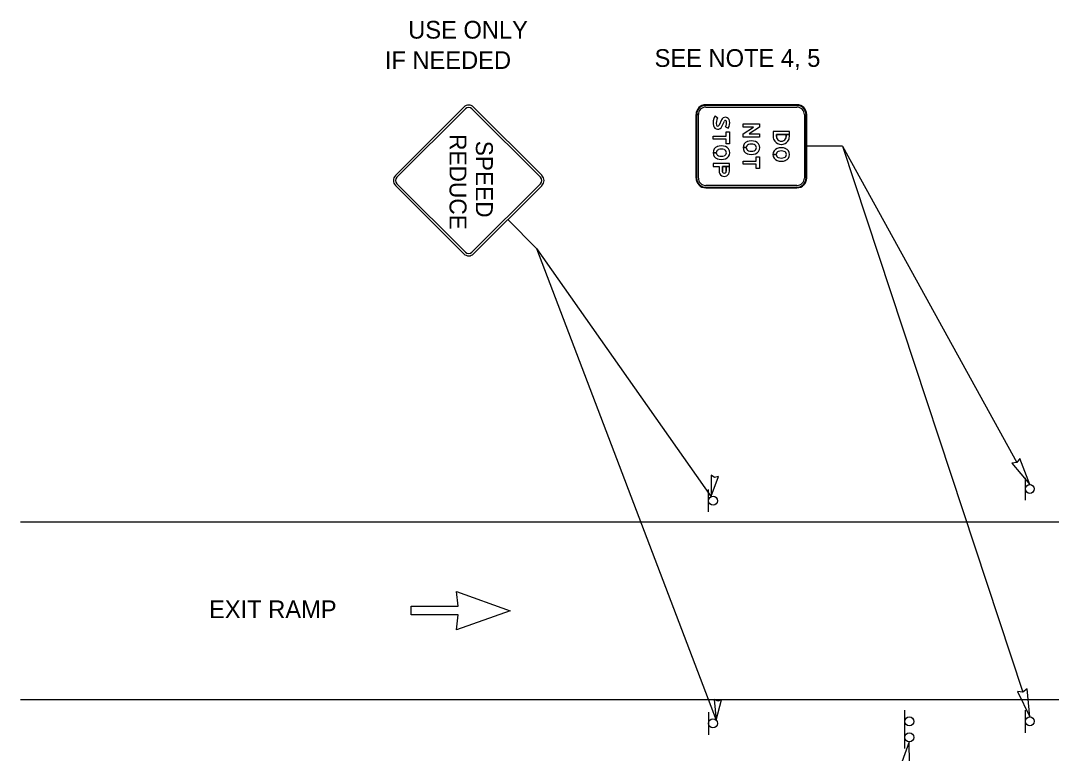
# Model space of a CAD drawing. Extents: x 46672 to 47298, y 5424 to 5742.
# Drawn here: x 47010.2 to 47173.2, y 5620.1 to 5736 of the extents above; entities that cross this region are included whole.
import ezdxf

# ---------------------------------------------------------------- set-up
doc = ezdxf.new("R2010")
doc.units = 0
for name, color, linetype in [('GSBWFill', 7, 'Continuous'), ('SheetBorder_dp', 7, 'Continuous'), ('SheetLines_dp', 7, 'Continuous'), ('TextAlert', 7, 'Continuous'), ('TextMisc', 7, 'Continuous'), ('TextNotes', 7, 'Continuous')]:
    doc.layers.add(name, color=color, linetype=linetype)

msp = doc.modelspace()

# ---------------------------------------------------------------- linework, layer by layer
at = {"layer": 'GSBWFill'}
for p, q in [((47010.15, 5656.76), (47280.21, 5656.76)), ((47010.15, 5628.64), (47280.21, 5628.64))]:
    msp.add_line(p, q, dxfattribs=at)
at = {"layer": 'SheetLines_dp'}
for p, q in [((47140.16, 5716.16), (47134.47, 5716.15)), ((47140.16, 5716.16), (47168.68, 5629.83)), ((47140.16, 5716.16), (47167.73, 5666.13)), ((47091.75, 5700.01), (47087.2, 5704.56)), ((47091.75, 5700.01), (47120.15, 5625.36)), ((47091.75, 5700.01), (47119.36, 5660.72))]:
    msp.add_line(p, q, dxfattribs=at)
for points in [[(47169.77, 5662.66), (47168.21, 5666.79), (47167.73, 5666.13), (47166.9, 5666.01)], [(47119.39, 5660.79), (47120.51, 5663.92), (47119.91, 5663.78), (47119.38, 5664.11)], [(47169.77, 5625.9), (47169.33, 5630.34), (47168.68, 5629.83), (47167.84, 5629.93)], [(47120.15, 5625.36), (47120.98, 5628.58), (47120.4, 5628.39), (47119.84, 5628.67)], [(47150.7, 5621.96), (47149.54, 5618.72), (47150.16, 5618.86), (47150.71, 5618.52)]]:
    msp.add_lwpolyline(points, close=True, dxfattribs=at)
at = {"layer": 'TextAlert'}
for p, q in [((47079.33, 5643.4), (47079.09, 5645.74)), ((47079.09, 5645.74), (47087.58, 5642.7)), ((47071.9, 5642.04), (47071.91, 5643.42)), ((47071.91, 5643.42), (47079.33, 5643.4)), ((47087.58, 5642.7), (47079.08, 5639.69)), ((47079.33, 5642.03), (47071.9, 5642.04)), ((47079.08, 5639.69), (47079.33, 5642.03))]:
    msp.add_line(p, q, dxfattribs=at)
at = {"layer": 'TextMisc'}
for p, q in [((47169.05, 5663.72), (47169.04, 5660.16)), ((47118.95, 5658.33), (47118.95, 5661.88)), ((47118.93, 5626.62), (47118.92, 5623.07)), ((47149.98, 5620.9), (47149.98, 5626.94)), ((47169.04, 5626.96), (47169.04, 5623.4))]:
    msp.add_line(p, q, dxfattribs=at)
for centre in [(47169.77, 5661.96), (47119.67, 5660.09), (47119.65, 5624.87), (47150.7, 5625.18), (47169.77, 5625.2), (47150.7, 5622.66)]:
    msp.add_circle(centre, 0.703, dxfattribs=at)
at = {"layer": 'TextNotes'}
for p, q in [((47069.42, 5711.52), (47080.24, 5722.35)), ((47081.79, 5722.35), (47092.62, 5711.52)), ((47132.93, 5722.72), (47118.52, 5722.72)), ((47132.93, 5722.72), (47118.52, 5722.72)), ((47118.52, 5722.69), (47132.93, 5722.69)), ((47132.93, 5722.62), (47118.52, 5722.62)), ((47118.52, 5722.35), (47132.93, 5722.35)), ((47069.67, 5711.26), (47080.5, 5722.09)), ((47081.53, 5722.09), (47092.36, 5711.26)), ((47116.97, 5721.17), (47116.97, 5711.14)), ((47116.97, 5721.17), (47117, 5721.17)), ((47117, 5721.17), (47116.97, 5721.17)), ((47116.97, 5721.17), (47116.97, 5711.14)), ((47117, 5711.14), (47117, 5721.17)), ((47117.07, 5721.17), (47117.34, 5721.17)), ((47117.07, 5721.16), (47117.07, 5711.14)), ((47117.34, 5721.16), (47117.07, 5721.16)), ((47117.34, 5711.14), (47117.34, 5721.16)), ((47120.39, 5720.65), (47119.96, 5720.91)), ((47120.39, 5720.65), (47119.96, 5720.91)), ((47120.39, 5720.65), (47119.96, 5720.91)), ((47134.11, 5721.17), (47134.11, 5711.14)), ((47134.38, 5711.14), (47134.38, 5721.17)), ((47134.45, 5721.17), (47134.45, 5711.14)), ((47134.47, 5711.14), (47134.47, 5721.17)), ((47134.47, 5711.14), (47134.47, 5721.17)), ((47120.99, 5720.34), (47120.61, 5719.48)), ((47120.99, 5720.34), (47120.61, 5719.48)), ((47120.99, 5720.34), (47120.61, 5719.48)), ((47121.08, 5719.27), (47121.45, 5720.14)), ((47121.08, 5719.27), (47121.45, 5720.14)), ((47121.08, 5719.27), (47121.45, 5720.14)), ((47121.63, 5719.25), (47122.08, 5719.01)), ((47121.63, 5719.25), (47122.08, 5719.01)), ((47121.63, 5719.25), (47122.08, 5719.01)), ((47129.19, 5717.68), (47129.19, 5717.68)), ((47129.7, 5717.68), (47129.7, 5718.01)), ((47129.7, 5717.68), (47129.7, 5718.01)), ((47129.7, 5717.68), (47129.7, 5717.68)), ((47124.4, 5715.94), (47124.91, 5715.94)), ((47124.91, 5715.94), (47124.4, 5715.94)), ((47124.4, 5715.94), (47124.91, 5715.94)), ((47124.91, 5715.94), (47124.4, 5715.94)), ((47119.67, 5715.14), (47120.18, 5715.14)), ((47120.18, 5715.14), (47119.67, 5715.14)), ((47119.67, 5715.14), (47120.18, 5715.14)), ((47120.18, 5715.14), (47119.67, 5715.14)), ((47129.14, 5714.86), (47129.65, 5714.86)), ((47129.65, 5714.86), (47129.14, 5714.86)), ((47129.14, 5714.86), (47129.65, 5714.86)), ((47129.65, 5714.86), (47129.14, 5714.86)), ((47120.63, 5712.96), (47120.63, 5712.2)), ((47121.14, 5712.96), (47121.14, 5712.23)), ((47080.24, 5699.15), (47069.42, 5709.97)), ((47080.5, 5699.4), (47069.67, 5710.23)), ((47092.36, 5710.23), (47081.53, 5699.4)), ((47092.62, 5709.97), (47081.79, 5699.15)), ((47132.93, 5709.95), (47118.52, 5709.95)), ((47118.52, 5709.68), (47132.93, 5709.68)), ((47132.93, 5709.62), (47118.52, 5709.62)), ((47118.52, 5709.59), (47132.93, 5709.59)), ((47118.52, 5709.59), (47132.93, 5709.59))]:
    msp.add_line(p, q, dxfattribs=at)
for points in [[(47127, 5719.69), (47127, 5719.18), (47125.39, 5718.13), (47127, 5718.13), (47127, 5717.62), (47124.45, 5717.62), (47124.45, 5718.12), (47126.07, 5719.18), (47124.45, 5719.18), (47124.45, 5719.69)], [(47127, 5719.69), (47127, 5719.18), (47125.39, 5718.13), (47127, 5718.13), (47127, 5717.62), (47124.45, 5717.62), (47124.45, 5718.12), (47126.07, 5719.18), (47124.45, 5719.18), (47124.45, 5719.69)], [(47127, 5719.69), (47127, 5719.18), (47125.39, 5718.13), (47127, 5718.13), (47127, 5717.62), (47124.45, 5717.62), (47124.45, 5718.12), (47126.07, 5719.18), (47124.45, 5719.18), (47124.45, 5719.69)], [(47119.71, 5717.26), (47119.71, 5717.77), (47121.75, 5717.77), (47121.75, 5718.46), (47122.26, 5718.46), (47122.26, 5716.57), (47121.75, 5716.57), (47121.75, 5717.26)], [(47119.71, 5717.26), (47119.71, 5717.77), (47121.75, 5717.77), (47121.75, 5718.46), (47122.26, 5718.46), (47122.26, 5716.57), (47121.75, 5716.57), (47121.75, 5717.26)], [(47119.71, 5717.26), (47119.71, 5717.77), (47121.75, 5717.77), (47121.75, 5718.46), (47122.26, 5718.46), (47122.26, 5716.57), (47121.75, 5716.57), (47121.75, 5717.26)], [(47124.45, 5713.31), (47124.45, 5713.82), (47126.49, 5713.82), (47126.49, 5714.51), (47127, 5714.51), (47127, 5712.62), (47126.49, 5712.62), (47126.49, 5713.31)], [(47124.45, 5713.31), (47124.45, 5713.82), (47126.49, 5713.82), (47126.49, 5714.51), (47127, 5714.51), (47127, 5712.62), (47126.49, 5712.62), (47126.49, 5713.31)], [(47124.45, 5713.31), (47124.45, 5713.82), (47126.49, 5713.82), (47126.49, 5714.51), (47127, 5714.51), (47127, 5712.62), (47126.49, 5712.62), (47126.49, 5713.31)]]:
    msp.add_lwpolyline(points, close=True, dxfattribs=at)
for points in [[(47131.74, 5717.68), (47131.74, 5718.51), (47129.19, 5718.51), (47129.19, 5717.68)], [(47129.7, 5718.01), (47131.74, 5718.01), (47131.74, 5718.51), (47129.19, 5718.51), (47129.19, 5717.68)], [(47129.7, 5718.01), (47131.74, 5718.01), (47131.74, 5718.51), (47129.19, 5718.51), (47129.19, 5717.68)], [(47131.23, 5717.68), (47131.23, 5718.01), (47129.7, 5718.01), (47129.7, 5717.68)], [(47131.74, 5717.68), (47131.74, 5718.01), (47131.23, 5718.01), (47131.23, 5717.68)], [(47131.74, 5717.68), (47131.74, 5718.01), (47131.23, 5718.01), (47131.23, 5717.68)], [(47122.26, 5712.2), (47122.26, 5713.46), (47119.71, 5713.46), (47119.71, 5712.96), (47120.63, 5712.96)], [(47122.26, 5713.46), (47119.71, 5713.46), (47119.71, 5712.96), (47120.63, 5712.96), (47120.63, 5712.2)], [(47122.26, 5713.46), (47119.71, 5713.46), (47119.71, 5712.96), (47120.63, 5712.96), (47120.63, 5712.2)], [(47121.14, 5712.23), (47121.14, 5712.96), (47122.26, 5712.96), (47122.26, 5713.46)], [(47121.14, 5712.23), (47121.14, 5712.96), (47122.26, 5712.96), (47122.26, 5713.46)], [(47121.75, 5712.23), (47121.75, 5712.96), (47121.14, 5712.96)], [(47122.26, 5712.2), (47122.26, 5712.96), (47121.75, 5712.96), (47121.75, 5712.23)], [(47122.26, 5712.2), (47122.26, 5712.96), (47121.75, 5712.96), (47121.75, 5712.23)]]:
    msp.add_lwpolyline(points, dxfattribs=at)
for centre, radius, start, end in [((47081.02, 5721.58), 1.09, 45, 135), ((47081.02, 5721.58), 0.729, 45, 135), ((47118.52, 5721.17), 1.55, 90, 180), ((47118.52, 5721.17), 1.55, 90, 180), ((47118.52, 5721.17), 1.52, 90, 180), ((47118.52, 5721.17), 1.46, 90, 180), ((47118.52, 5721.17), 1.18, 90, 180), ((47132.93, 5721.17), 1.55, 0, 90), ((47132.93, 5721.17), 1.55, 0, 90), ((47132.93, 5721.17), 1.52, 0, 90), ((47132.93, 5721.17), 1.46, 0, 90), ((47132.93, 5721.17), 1.18, 0, 90), ((47121.66, 5719.88), 1.99, 148.7193, 194.4775), ((47121.66, 5719.88), 1.99, 148.7193, 194.4775), ((47121.66, 5719.88), 1.99, 148.7193, 194.4775), ((47121.66, 5719.88), 1.48, 148.7193, 194.4775), ((47121.66, 5719.88), 1.48, 148.7193, 194.4775), ((47121.66, 5719.88), 1.48, 148.7193, 194.4775), ((47121.61, 5720.07), 0.676, 9.4877, 156.3243), ((47121.61, 5720.07), 0.676, 9.4877, 156.3243), ((47121.61, 5720.07), 0.676, 9.4877, 156.3243), ((47120.42, 5719.56), 0.714, 194.4775, 336.3243), ((47120.42, 5719.56), 0.714, 194.4775, 336.3243), ((47120.42, 5719.56), 0.714, 194.4775, 336.3243), ((47120.42, 5719.56), 0.204, 194.4775, 336.3243), ((47120.42, 5719.56), 0.204, 194.4775, 336.3243), ((47120.42, 5719.56), 0.204, 194.4775, 336.3243), ((47121.61, 5720.07), 0.166, 9.4877, 156.3243), ((47121.61, 5720.07), 0.166, 9.4877, 156.3243), ((47121.61, 5720.07), 0.166, 9.4877, 156.3243), ((47120.46, 5719.88), 1.33, 331.8214, 9.4877), ((47120.46, 5719.88), 1.33, 331.8214, 9.4877), ((47120.46, 5719.88), 1.33, 331.8214, 9.4877), ((47120.46, 5719.88), 1.84, 331.8214, 9.4877), ((47120.46, 5719.88), 1.84, 331.8214, 9.4877), ((47120.46, 5719.88), 1.84, 331.8214, 9.4877), ((47070.19, 5710.75), 1.09, 135, 225), ((47070.19, 5710.75), 0.729, 135, 225), ((47091.84, 5710.75), 0.729, 315, 45), ((47091.84, 5710.75), 1.09, 315, 45), ((47118.52, 5711.14), 1.55, 180, 270), ((47118.52, 5711.14), 1.55, 180, 270), ((47118.52, 5711.14), 1.52, 180, 270), ((47118.52, 5711.14), 1.46, 180, 270), ((47118.52, 5711.14), 1.18, 180, 270), ((47132.93, 5711.14), 1.46, 270, 0), ((47132.93, 5711.14), 1.18, 270, 0), ((47132.93, 5711.14), 1.55, 270, 0), ((47132.93, 5711.14), 1.52, 270, 0), ((47132.93, 5711.14), 1.55, 270, 0), ((47081.02, 5699.92), 0.729, 225, 315), ((47081.02, 5699.92), 1.09, 225, 315)]:
    msp.add_arc(centre, radius, start, end, dxfattribs=at)
for centre, major_axis, ratio, start_param, end_param in [((47130.3, 5717.65), (1.12, 0), 0.992015, 3.111301, 3.802985), ((47130.3, 5717.65), (1.12, 0), 0.992015, 3.111301, 3.802985), ((47130.3, 5717.65), (1.12, 0), 0.992015, 3.111301, 3.802985), ((47130.39, 5717.67), (0.69, 0), 0.992015, 3.123742, 3.672538), ((47130.39, 5717.67), (0.69, 0), 0.992015, 3.123742, 3.672538), ((47130.39, 5717.67), (0.69, 0), 0.992015, 3.123742, 3.672538), ((47130.44, 5717.71), (0.762, 0), 0.992015, 3.689617, 4.738495), ((47130.44, 5717.71), (0.762, 0), 0.992015, 3.689617, 4.738495), ((47130.44, 5717.71), (0.762, 0), 0.992015, 3.689617, 4.738495), ((47130.48, 5717.71), (0.762, 0), 0.992015, 4.686283, 5.735161), ((47130.48, 5717.71), (0.762, 0), 0.992015, 4.686283, 5.735161), ((47130.48, 5717.71), (0.762, 0), 0.992015, 4.686283, 5.735161), ((47130.54, 5717.67), (0.69, 0), 0.992015, 5.75224, 6.301036), ((47130.54, 5717.67), (0.69, 0), 0.992015, 5.75224, 6.301036), ((47130.54, 5717.67), (0.69, 0), 0.992015, 5.75224, 6.301036), ((47130.62, 5717.65), (1.12, 0), 0.992015, 5.621793, 6.313477), ((47130.62, 5717.65), (1.12, 0), 0.992015, 5.621793, 6.313477), ((47130.62, 5717.65), (1.12, 0), 0.992015, 5.621793, 6.313477), ((47120.69, 5715.14), (1.02, 0), 0.999996, 1.91299, 4.370195), ((47120.69, 5715.14), (1.02, 0), 0.999996, 1.91299, 3.141593), ((47120.69, 5715.14), (1.02, 0), 0.999996, 1.91299, 3.141593), ((47120.69, 5715.14), (0.51, 0), 0.999996, 1.91299, 4.370195), ((47120.69, 5715.14), (0.51, 0), 0.999996, 1.91299, 3.141593), ((47120.69, 5715.14), (0.51, 0), 0.999996, 1.91299, 3.141593), ((47120.98, 5714.32), (1.9, 0), 0.999996, 1.228603, 1.91299), ((47120.98, 5714.32), (1.9, 0), 0.999996, 1.228603, 1.91299), ((47120.98, 5714.32), (1.9, 0), 0.999996, 1.228603, 1.91299), ((47120.98, 5714.32), (1.39, 0), 0.999996, 1.228603, 1.91299), ((47120.98, 5714.32), (1.39, 0), 0.999996, 1.228603, 1.91299), ((47120.98, 5714.32), (1.39, 0), 0.999996, 1.228603, 1.91299), ((47121.28, 5715.14), (0.51, 0), 0.999996, 5.054583, 7.511788), ((47121.28, 5715.14), (0.51, 0), 0.999996, 5.054583, 7.511788), ((47121.28, 5715.14), (0.51, 0), 0.999996, 5.054583, 7.511788), ((47121.28, 5715.14), (1.02, 0), 0.999996, 5.054583, 7.511788), ((47121.28, 5715.14), (1.02, 0), 0.999996, 5.054583, 7.511788), ((47121.28, 5715.14), (1.02, 0), 0.999996, 5.054583, 7.511788), ((47125.43, 5715.94), (1.02, 0), 0.999997, 1.91299, 4.370195), ((47125.43, 5715.94), (1.02, 0), 0.999997, 1.91299, 3.141593), ((47125.43, 5715.94), (1.02, 0), 0.999997, 1.91299, 3.141593), ((47125.43, 5715.94), (1.02, 0), 0.999997, 3.141718, 4.370195), ((47125.43, 5715.94), (1.02, 0), 0.999997, 3.141718, 4.370195), ((47125.43, 5715.94), (0.51, 0), 0.999997, 1.91299, 4.370195), ((47125.43, 5715.94), (0.51, 0), 0.999997, 1.91299, 3.141593), ((47125.43, 5715.94), (0.51, 0), 0.999997, 1.91299, 3.141593), ((47125.43, 5715.94), (0.51, 0), 0.999997, 3.141843, 4.370195), ((47125.43, 5715.94), (0.51, 0), 0.999997, 3.141843, 4.370195), ((47125.72, 5715.11), (1.9, 0), 0.999997, 1.228603, 1.91299), ((47125.72, 5715.11), (1.9, 0), 0.999997, 1.228603, 1.91299), ((47125.72, 5715.11), (1.9, 0), 0.999997, 1.228603, 1.91299), ((47125.72, 5715.11), (1.39, 0), 0.999997, 1.228603, 1.91299), ((47125.72, 5715.11), (1.39, 0), 0.999997, 1.228603, 1.91299), ((47125.72, 5715.11), (1.39, 0), 0.999997, 1.228603, 1.91299), ((47126.02, 5715.94), (0.51, 0), 0.999997, 5.054583, 7.511788), ((47126.02, 5715.94), (0.51, 0), 0.999997, 5.054583, 7.511788), ((47126.02, 5715.94), (0.51, 0), 0.999997, 5.054583, 7.511788), ((47126.02, 5715.94), (1.02, 0), 0.999997, 5.054583, 7.511788), ((47126.02, 5715.94), (1.02, 0), 0.999997, 5.054583, 7.511788), ((47126.02, 5715.94), (1.02, 0), 0.999997, 5.054583, 7.511788), ((47130.16, 5714.86), (1.02, 0), 0.999995, 1.91299, 4.370195), ((47130.16, 5714.86), (1.02, 0), 0.999995, 1.91299, 3.141593), ((47130.16, 5714.86), (1.02, 0), 0.999995, 1.91299, 3.141593), ((47130.45, 5717.71), (1.27, 0), 0.992015, 3.769463, 4.722379), ((47130.45, 5717.71), (1.27, 0), 0.992015, 3.769463, 4.722379), ((47130.45, 5717.71), (1.27, 0), 0.992015, 3.769463, 4.722379), ((47130.46, 5714.03), (1.9, 0), 0.999995, 1.228603, 1.91299), ((47130.46, 5714.03), (1.9, 0), 0.999995, 1.228603, 1.91299), ((47130.46, 5714.03), (1.9, 0), 0.999995, 1.228603, 1.91299), ((47130.48, 5717.71), (1.27, 0), 0.992015, 4.702399, 5.655315), ((47130.48, 5717.71), (1.27, 0), 0.992015, 4.702399, 5.655315), ((47130.48, 5717.71), (1.27, 0), 0.992015, 4.702399, 5.655315), ((47130.75, 5714.86), (1.02, 0), 0.999995, 5.054583, 7.511788), ((47130.75, 5714.86), (1.02, 0), 0.999995, 5.054583, 7.511788), ((47130.75, 5714.86), (1.02, 0), 0.999995, 5.054583, 7.511788), ((47120.69, 5715.14), (1.02, 0), 0.999996, 3.141718, 4.370195), ((47120.69, 5715.14), (1.02, 0), 0.999996, 3.141718, 4.370195), ((47120.69, 5715.14), (0.51, 0), 0.999996, 3.141843, 4.370195), ((47120.69, 5715.14), (0.51, 0), 0.999996, 3.141843, 4.370195), ((47120.98, 5715.97), (1.9, 0), 0.999996, 4.370195, 5.054583), ((47120.98, 5715.97), (1.9, 0), 0.999996, 4.370195, 5.054583), ((47120.98, 5715.97), (1.9, 0), 0.999996, 4.370195, 5.054583), ((47120.98, 5715.97), (1.39, 0), 0.999996, 4.370195, 5.054583), ((47120.98, 5715.97), (1.39, 0), 0.999996, 4.370195, 5.054583), ((47120.98, 5715.97), (1.39, 0), 0.999996, 4.370195, 5.054583), ((47125.72, 5716.76), (1.9, 0), 0.999997, 4.370195, 5.054583), ((47125.72, 5716.76), (1.9, 0), 0.999997, 4.370195, 5.054583), ((47125.72, 5716.76), (1.9, 0), 0.999997, 4.370195, 5.054583), ((47125.72, 5716.76), (1.39, 0), 0.999997, 4.370195, 5.054583), ((47125.72, 5716.76), (1.39, 0), 0.999997, 4.370195, 5.054583), ((47125.72, 5716.76), (1.39, 0), 0.999997, 4.370195, 5.054583), ((47130.16, 5714.86), (1.02, 0), 0.999995, 3.141718, 4.370195), ((47130.16, 5714.86), (1.02, 0), 0.999995, 3.141718, 4.370195), ((47130.16, 5714.86), (0.51, 0), 0.999995, 1.91299, 4.370195), ((47130.16, 5714.86), (0.51, 0), 0.999995, 1.91299, 3.141593), ((47130.16, 5714.86), (0.51, 0), 0.999995, 1.91299, 3.141593), ((47130.16, 5714.86), (0.51, 0), 0.999995, 3.141843, 4.370195), ((47130.16, 5714.86), (0.51, 0), 0.999995, 3.141843, 4.370195), ((47130.46, 5714.03), (1.39, 0), 0.999995, 1.228603, 1.91299), ((47130.46, 5714.03), (1.39, 0), 0.999995, 1.228603, 1.91299), ((47130.46, 5714.03), (1.39, 0), 0.999995, 1.228603, 1.91299), ((47130.46, 5715.69), (1.39, 0), 0.999995, 4.370195, 5.054583), ((47130.46, 5715.69), (1.39, 0), 0.999995, 4.370195, 5.054583), ((47130.46, 5715.69), (1.39, 0), 0.999995, 4.370195, 5.054583), ((47130.75, 5714.86), (0.51, 0), 0.999995, 5.054583, 7.511788), ((47130.75, 5714.86), (0.51, 0), 0.999995, 5.054583, 7.511788), ((47130.75, 5714.86), (0.51, 0), 0.999995, 5.054583, 7.511788), ((47130.46, 5715.69), (1.9, 0), 0.999995, 4.370195, 5.054583), ((47130.46, 5715.69), (1.9, 0), 0.999995, 4.370195, 5.054583), ((47130.46, 5715.69), (1.9, 0), 0.999995, 4.370195, 5.054583), ((47121.44, 5712.2), (0.817, 0), 0.985871, 3.140988, 6.28379), ((47121.44, 5712.2), (0.817, 0), 0.985871, 3.140988, 6.28379), ((47121.44, 5712.2), (0.817, 0), 0.985871, 3.140988, 6.28379), ((47121.44, 5712.2), (0.308, 0), 0.985871, 3.056611, 6.368167), ((47121.44, 5712.2), (0.308, 0), 0.985871, 3.056611, 6.368167), ((47121.44, 5712.2), (0.308, 0), 0.985871, 3.056611, 6.368167)]:
    msp.add_ellipse(centre, major_axis=major_axis, ratio=ratio, start_param=start_param, end_param=end_param, dxfattribs=at)

# ---------------------------------------------------------------- texts
at = {"layer": 'SheetBorder_dp'}
for s, p in [('USE ONLY', (47071.45, 5733.19)), ('IF NEEDED', (47067.75, 5728.39)), ('SEE NOTE 4, 5', (47110.42, 5728.72)), ('EXIT RAMP', (47039.95, 5641.52))]:
    msp.add_text(s, height=2.8, dxfattribs=at).set_placement(p)
at = {"layer": 'TextNotes'}
for s, height, p in [('REDUCE', 2.68, (47077.99, 5718.08)), ('SPEED', 2.68, (47082.16, 5717.03)), ('reportName:OOCEA10', 0.000364, (47134.48, 5716.15)), ('plotScale:71', 0.000364, (47134.48, 5716.15)), ('tableTextHeight:0.0710', 0.000364, (47134.48, 5716.15)), ('letterPositions:2', 0.000364, (47134.48, 5716.15)), ('inchesDisplay:0', 0.000364, (47134.48, 5716.15))]:
    msp.add_text(s, height=height, rotation=270, dxfattribs=at).set_placement(p)

doc.saveas('drawing.dxf')
